// Mitsubishi GX Works2 project: 定时器   PLC: FX1S

PROGRAM MAIN
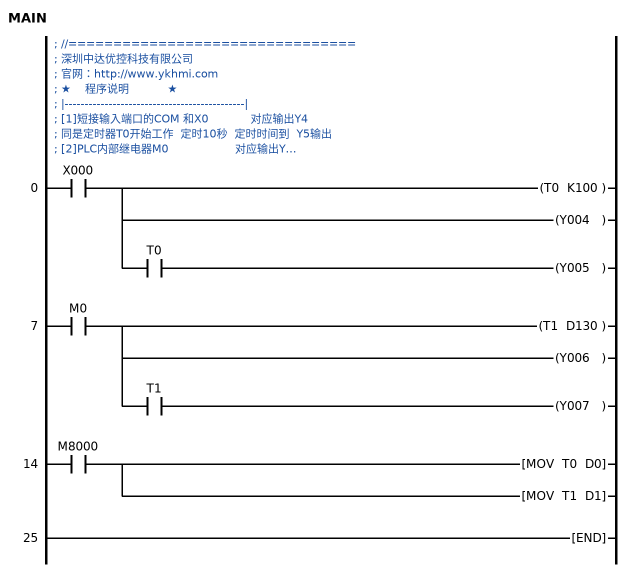
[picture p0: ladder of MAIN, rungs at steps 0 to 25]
; //================================
; 深圳中达优控科技有限公司
; 官网：http://www.ykhmi.com
; ★    程序说明           ★
; |---------------------------------------------|
; [1]短接输入端口的COM 和X0            对应输出Y4
; 同是定时器T0开始工作  定时10秒  定时时间到  Y5输出
; [2]PLC内部继电器M0                   对应输出Y6
; 同时定时器T1开始工作，定时时间设定为D130，定时时间到输出Y7
; [3] 定时器的经过值 T0传到 D0  T1传到D1
0     LD      X000
      OUT     T0 K100
      OUT     Y004
      AND     T0
      OUT     Y005
7     LD      M0
      OUT     T1 D130
      OUT     Y006
      AND     T1
      OUT     Y007
14    LD      M8000
      MOV     T0 D0
      MOV     T1 D1
25    END
END_PROGRAM
